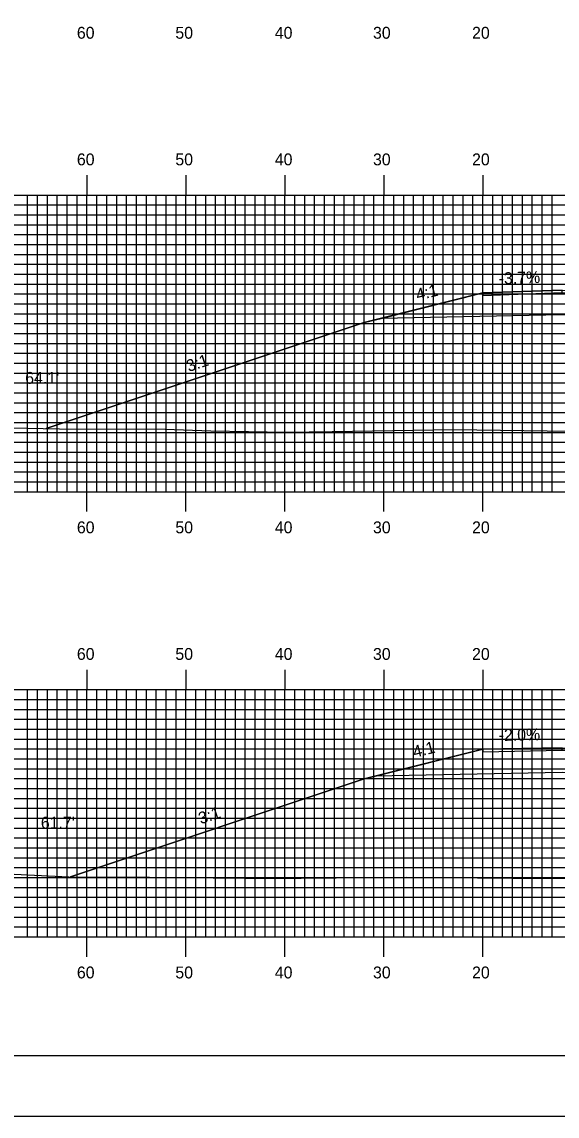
# Model space of a CAD drawing. Extents: x 1815309 to 1815652, y 442591 to 442811.
# Drawn here: x 1815408 to 1815462, y 442590.5 to 442701.2 of the extents above; entities that cross this region are included whole.
import ezdxf

# ---------------------------------------------------------------- set-up
doc = ezdxf.new("R2010")
doc.units = 0
for name, color, linetype in [('ANNOTATION', 7, 'Continuous'), ('BORDER', 7, 'Continuous'), ('D_Roadway_Centerline', 7, 'Continuous'), ('D_Roadway_Edge_Shoulder', 7, 'Continuous'), ('D_Roadway_SlopeLines', 7, 'Continuous'), ('D_Roadway_SubGrade', 7, 'Continuous'), ('D_Text_Standard', 7, 'Continuous'), ('H_V ANNOTATION', 7, 'Continuous'), ('MAJOR', 7, 'Continuous'), ('MINOR', 7, 'Continuous'), ('PLOT BOUNDARY', 7, 'Continuous'), ('S_Roadway_Centerline', 7, 'Continuous')]:
    doc.layers.add(name, color=color, linetype=linetype)

msp = doc.modelspace()

# ---------------------------------------------------------------- linework, layer by layer
at = {"layer": 'BORDER'}
msp.add_lwpolyline([(1815324.93, 442596.67), (1815644.93, 442596.67), (1815644.93, 442806.67), (1815324.93, 442806.67)], close=True, dxfattribs=at)
at = {"layer": 'D_Roadway_Centerline'}
for points in [[(1815410.41, 442660.06), (1815442.53, 442670.77), (1815444.25, 442671.2), (1815454.53, 442673.77), (1815462.53, 442674.06), (1815474.53, 442673.77), (1815486.53, 442673.48), (1815494.53, 442673.16), (1815505.06, 442670.53), (1815506.53, 442670.16), (1815538.16, 442659.62)], [(1815412.86, 442614.74), (1815442.53, 442624.63), (1815443.66, 442624.92), (1815454.53, 442627.63), (1815462.53, 442627.79), (1815474.53, 442627.27), (1815486.53, 442626.74), (1815494.53, 442626.39), (1815506.53, 442623.39), (1815506.66, 442623.36), (1815532.71, 442614.67)]]:
    msp.add_lwpolyline(points, dxfattribs=at)
at = {"layer": 'D_Roadway_Edge_Shoulder'}
for points in [[(1815462.53, 442674.06), (1815454.53, 442673.77), (1815454.53, 442673.52), (1815462.53, 442673.81)], [(1815462.53, 442627.79), (1815454.53, 442627.63), (1815454.53, 442627.38), (1815462.53, 442627.54)]]:
    msp.add_lwpolyline(points, close=True, dxfattribs=at)
at = {"layer": 'D_Roadway_SlopeLines'}
for points in [[(1815454.53, 442673.77), (1815442.53, 442670.77), (1815410.41, 442660.06)], [(1815454.53, 442627.63), (1815442.53, 442624.63), (1815412.86, 442614.74)]]:
    msp.add_lwpolyline(points, dxfattribs=at)
at = {"layer": 'D_Roadway_SubGrade'}
for points in [[(1815462.53, 442671.56), (1815444.25, 442671.2), (1815454.53, 442673.77), (1815454.53, 442673.52), (1815462.53, 442673.81), (1815474.53, 442673.52), (1815486.53, 442673.23), (1815494.53, 442672.91), (1815494.53, 442673.16), (1815505.06, 442670.53), (1815486.53, 442670.98), (1815474.53, 442671.27)], [(1815462.53, 442625.29), (1815443.66, 442624.92), (1815454.53, 442627.63), (1815454.53, 442627.38), (1815462.53, 442627.54), (1815474.53, 442627.02), (1815486.53, 442626.49), (1815494.53, 442626.14), (1815494.53, 442626.39), (1815506.66, 442623.36), (1815486.53, 442624.24), (1815474.53, 442624.77)]]:
    msp.add_lwpolyline(points, close=True, dxfattribs=at)
at = {"layer": 'MAJOR'}
for p, q in [((1815414.53, 442685.67), (1815414.53, 442683.67)), ((1815424.53, 442685.67), (1815424.53, 442683.67)), ((1815434.53, 442685.67), (1815434.53, 442683.67)), ((1815444.53, 442685.67), (1815444.53, 442683.67)), ((1815454.53, 442685.67), (1815454.53, 442683.67)), ((1815334.53, 442683.67), (1815614.53, 442683.67)), ((1815334.53, 442683.67), (1815614.53, 442683.67)), ((1815414.53, 442653.67), (1815414.53, 442683.67)), ((1815424.53, 442653.67), (1815424.53, 442683.67)), ((1815434.53, 442653.67), (1815434.53, 442683.67)), ((1815444.53, 442653.67), (1815444.53, 442683.67)), ((1815454.53, 442653.67), (1815454.53, 442683.67)), ((1815334.53, 442678.67), (1815614.53, 442678.67)), ((1815334.53, 442673.67), (1815614.53, 442673.67)), ((1815334.53, 442668.67), (1815614.53, 442668.67)), ((1815334.53, 442663.67), (1815614.53, 442663.67)), ((1815334.53, 442658.67), (1815614.53, 442658.67)), ((1815334.53, 442653.67), (1815614.53, 442653.67)), ((1815334.53, 442653.67), (1815614.53, 442653.67)), ((1815414.53, 442651.66), (1815414.53, 442653.67)), ((1815424.53, 442651.66), (1815424.53, 442653.67)), ((1815434.53, 442651.66), (1815434.53, 442653.67)), ((1815444.53, 442651.66), (1815444.53, 442653.67)), ((1815454.53, 442651.66), (1815454.53, 442653.67)), ((1815414.53, 442635.67), (1815414.53, 442633.67)), ((1815424.53, 442635.67), (1815424.53, 442633.67)), ((1815434.53, 442635.67), (1815434.53, 442633.67)), ((1815444.53, 442635.67), (1815444.53, 442633.67)), ((1815454.53, 442635.67), (1815454.53, 442633.67)), ((1815334.53, 442633.67), (1815614.53, 442633.67)), ((1815334.53, 442633.67), (1815614.53, 442633.67)), ((1815414.53, 442608.67), (1815414.53, 442633.67)), ((1815424.53, 442608.67), (1815424.53, 442633.67)), ((1815434.53, 442608.67), (1815434.53, 442633.67)), ((1815444.53, 442608.67), (1815444.53, 442633.67)), ((1815454.53, 442608.67), (1815454.53, 442633.67)), ((1815334.53, 442628.67), (1815614.53, 442628.67)), ((1815334.53, 442623.67), (1815614.53, 442623.67)), ((1815334.53, 442618.67), (1815614.53, 442618.67)), ((1815334.53, 442613.67), (1815614.53, 442613.67)), ((1815334.53, 442608.67), (1815614.53, 442608.67)), ((1815334.53, 442608.67), (1815614.53, 442608.67)), ((1815414.53, 442606.66), (1815414.53, 442608.67)), ((1815424.53, 442606.66), (1815424.53, 442608.67)), ((1815434.53, 442606.66), (1815434.53, 442608.67)), ((1815444.53, 442606.66), (1815444.53, 442608.67)), ((1815454.53, 442606.66), (1815454.53, 442608.67))]:
    msp.add_line(p, q, dxfattribs=at)
at = {"layer": 'MINOR'}
for p, q in [((1815408.53, 442653.67), (1815408.53, 442683.67)), ((1815409.53, 442653.67), (1815409.53, 442683.67)), ((1815410.53, 442653.67), (1815410.53, 442683.67)), ((1815411.53, 442653.67), (1815411.53, 442683.67)), ((1815412.53, 442653.67), (1815412.53, 442683.67)), ((1815413.53, 442653.67), (1815413.53, 442683.67)), ((1815415.53, 442653.67), (1815415.53, 442683.67)), ((1815416.53, 442653.67), (1815416.53, 442683.67)), ((1815417.53, 442653.67), (1815417.53, 442683.67)), ((1815418.53, 442653.67), (1815418.53, 442683.67)), ((1815419.53, 442653.67), (1815419.53, 442683.67)), ((1815420.53, 442653.67), (1815420.53, 442683.67)), ((1815421.53, 442653.67), (1815421.53, 442683.67)), ((1815422.53, 442653.67), (1815422.53, 442683.67)), ((1815423.53, 442653.67), (1815423.53, 442683.67)), ((1815425.53, 442653.67), (1815425.53, 442683.67)), ((1815426.53, 442653.67), (1815426.53, 442683.67)), ((1815427.53, 442653.67), (1815427.53, 442683.67)), ((1815428.53, 442653.67), (1815428.53, 442683.67)), ((1815429.53, 442653.67), (1815429.53, 442683.67)), ((1815430.53, 442653.67), (1815430.53, 442683.67)), ((1815431.53, 442653.67), (1815431.53, 442683.67)), ((1815432.53, 442653.67), (1815432.53, 442683.67)), ((1815433.53, 442653.67), (1815433.53, 442683.67)), ((1815435.53, 442653.67), (1815435.53, 442683.67)), ((1815436.53, 442653.67), (1815436.53, 442683.67)), ((1815437.53, 442653.67), (1815437.53, 442683.67)), ((1815438.53, 442653.67), (1815438.53, 442683.67)), ((1815439.53, 442653.67), (1815439.53, 442683.67)), ((1815440.53, 442653.67), (1815440.53, 442683.67)), ((1815441.53, 442653.67), (1815441.53, 442683.67)), ((1815442.53, 442653.67), (1815442.53, 442683.67)), ((1815443.53, 442653.67), (1815443.53, 442683.67)), ((1815445.53, 442653.67), (1815445.53, 442683.67)), ((1815446.53, 442653.67), (1815446.53, 442683.67)), ((1815447.53, 442653.67), (1815447.53, 442683.67)), ((1815448.53, 442653.67), (1815448.53, 442683.67)), ((1815449.53, 442653.67), (1815449.53, 442683.67)), ((1815450.53, 442653.67), (1815450.53, 442683.67)), ((1815451.53, 442653.67), (1815451.53, 442683.67)), ((1815452.53, 442653.67), (1815452.53, 442683.67)), ((1815453.53, 442653.67), (1815453.53, 442683.67)), ((1815455.53, 442653.67), (1815455.53, 442683.67)), ((1815456.53, 442653.67), (1815456.53, 442683.67)), ((1815457.53, 442653.67), (1815457.53, 442683.67)), ((1815458.53, 442653.67), (1815458.53, 442683.67)), ((1815459.53, 442653.67), (1815459.53, 442683.67)), ((1815460.53, 442653.67), (1815460.53, 442683.67)), ((1815461.53, 442653.67), (1815461.53, 442683.67)), ((1815334.53, 442682.67), (1815614.53, 442682.67)), ((1815334.53, 442681.67), (1815614.53, 442681.67)), ((1815334.53, 442680.67), (1815614.53, 442680.67)), ((1815334.53, 442679.67), (1815614.53, 442679.67)), ((1815334.53, 442677.67), (1815614.53, 442677.67)), ((1815334.53, 442676.67), (1815614.53, 442676.67)), ((1815334.53, 442675.67), (1815614.53, 442675.67)), ((1815334.53, 442674.67), (1815614.53, 442674.67)), ((1815334.53, 442672.67), (1815614.53, 442672.67)), ((1815334.53, 442671.67), (1815614.53, 442671.67)), ((1815334.53, 442670.67), (1815614.53, 442670.67)), ((1815334.53, 442669.67), (1815614.53, 442669.67)), ((1815334.53, 442667.67), (1815614.53, 442667.67)), ((1815334.53, 442666.67), (1815614.53, 442666.67)), ((1815334.53, 442665.67), (1815614.53, 442665.67)), ((1815334.53, 442664.67), (1815614.53, 442664.67)), ((1815334.53, 442662.67), (1815614.53, 442662.67)), ((1815334.53, 442661.67), (1815614.53, 442661.67)), ((1815334.53, 442660.67), (1815614.53, 442660.67)), ((1815334.53, 442659.67), (1815614.53, 442659.67)), ((1815334.53, 442657.67), (1815614.53, 442657.67)), ((1815334.53, 442656.67), (1815614.53, 442656.67)), ((1815334.53, 442655.67), (1815614.53, 442655.67)), ((1815334.53, 442654.67), (1815614.53, 442654.67)), ((1815408.53, 442608.67), (1815408.53, 442633.67)), ((1815409.53, 442608.67), (1815409.53, 442633.67)), ((1815410.53, 442608.67), (1815410.53, 442633.67)), ((1815411.53, 442608.67), (1815411.53, 442633.67)), ((1815412.53, 442608.67), (1815412.53, 442633.67)), ((1815413.53, 442608.67), (1815413.53, 442633.67)), ((1815415.53, 442608.67), (1815415.53, 442633.67)), ((1815416.53, 442608.67), (1815416.53, 442633.67)), ((1815417.53, 442608.67), (1815417.53, 442633.67)), ((1815418.53, 442608.67), (1815418.53, 442633.67)), ((1815419.53, 442608.67), (1815419.53, 442633.67)), ((1815420.53, 442608.67), (1815420.53, 442633.67)), ((1815421.53, 442608.67), (1815421.53, 442633.67)), ((1815422.53, 442608.67), (1815422.53, 442633.67)), ((1815423.53, 442608.67), (1815423.53, 442633.67)), ((1815425.53, 442608.67), (1815425.53, 442633.67)), ((1815426.53, 442608.67), (1815426.53, 442633.67)), ((1815427.53, 442608.67), (1815427.53, 442633.67)), ((1815428.53, 442608.67), (1815428.53, 442633.67)), ((1815429.53, 442608.67), (1815429.53, 442633.67)), ((1815430.53, 442608.67), (1815430.53, 442633.67)), ((1815431.53, 442608.67), (1815431.53, 442633.67)), ((1815432.53, 442608.67), (1815432.53, 442633.67)), ((1815433.53, 442608.67), (1815433.53, 442633.67)), ((1815435.53, 442608.67), (1815435.53, 442633.67)), ((1815436.53, 442608.67), (1815436.53, 442633.67)), ((1815437.53, 442608.67), (1815437.53, 442633.67)), ((1815438.53, 442608.67), (1815438.53, 442633.67)), ((1815439.53, 442608.67), (1815439.53, 442633.67)), ((1815440.53, 442608.67), (1815440.53, 442633.67)), ((1815441.53, 442608.67), (1815441.53, 442633.67)), ((1815442.53, 442608.67), (1815442.53, 442633.67)), ((1815443.53, 442608.67), (1815443.53, 442633.67)), ((1815445.53, 442608.67), (1815445.53, 442633.67)), ((1815446.53, 442608.67), (1815446.53, 442633.67)), ((1815447.53, 442608.67), (1815447.53, 442633.67)), ((1815448.53, 442608.67), (1815448.53, 442633.67)), ((1815449.53, 442608.67), (1815449.53, 442633.67)), ((1815450.53, 442608.67), (1815450.53, 442633.67)), ((1815451.53, 442608.67), (1815451.53, 442633.67)), ((1815452.53, 442608.67), (1815452.53, 442633.67)), ((1815453.53, 442608.67), (1815453.53, 442633.67)), ((1815455.53, 442608.67), (1815455.53, 442633.67)), ((1815456.53, 442608.67), (1815456.53, 442633.67)), ((1815457.53, 442608.67), (1815457.53, 442633.67)), ((1815458.53, 442608.67), (1815458.53, 442633.67)), ((1815459.53, 442608.67), (1815459.53, 442633.67)), ((1815460.53, 442608.67), (1815460.53, 442633.67)), ((1815461.53, 442608.67), (1815461.53, 442633.67)), ((1815334.53, 442632.67), (1815614.53, 442632.67)), ((1815334.53, 442631.67), (1815614.53, 442631.67)), ((1815334.53, 442630.67), (1815614.53, 442630.67)), ((1815334.53, 442629.67), (1815614.53, 442629.67)), ((1815334.53, 442627.67), (1815614.53, 442627.67)), ((1815334.53, 442626.67), (1815614.53, 442626.67)), ((1815334.53, 442625.67), (1815614.53, 442625.67)), ((1815334.53, 442624.67), (1815614.53, 442624.67)), ((1815334.53, 442622.67), (1815614.53, 442622.67)), ((1815334.53, 442621.67), (1815614.53, 442621.67)), ((1815334.53, 442620.67), (1815614.53, 442620.67)), ((1815334.53, 442619.67), (1815614.53, 442619.67)), ((1815334.53, 442617.67), (1815614.53, 442617.67)), ((1815334.53, 442616.67), (1815614.53, 442616.67)), ((1815334.53, 442615.67), (1815614.53, 442615.67)), ((1815334.53, 442614.67), (1815614.53, 442614.67)), ((1815334.53, 442612.67), (1815614.53, 442612.67)), ((1815334.53, 442611.67), (1815614.53, 442611.67)), ((1815334.53, 442610.67), (1815614.53, 442610.67)), ((1815334.53, 442609.67), (1815614.53, 442609.67))]:
    msp.add_line(p, q, dxfattribs=at)
at = {"layer": 'PLOT BOUNDARY'}
msp.add_lwpolyline([(1815308.75, 442590.55), (1815648.75, 442590.55), (1815648.75, 442810.55), (1815308.75, 442810.55)], close=True, dxfattribs=at)
at = {"layer": 'S_Roadway_Centerline'}
for points in [[(1815400.23, 442660.28), (1815411.74, 442660.03), (1815422.42, 442659.98), (1815427.06, 442659.83), (1815434.65, 442659.71), (1815439.29, 442659.76), (1815451.58, 442659.96), (1815465.79, 442659.75), (1815469.34, 442659.78), (1815479.38, 442659.77), (1815484.93, 442659.79), (1815492.58, 442659.87), (1815502.45, 442659.67), (1815518.01, 442659.62), (1815518.54, 442659.62), (1815518.67, 442659.62), (1815518.89, 442659.62), (1815536.31, 442659.64)], [(1815398.89, 442615.41), (1815413.38, 442614.72), (1815420.85, 442614.69), (1815430.49, 442614.62), (1815436.18, 442614.61), (1815446.82, 442614.7), (1815457.56, 442614.62), (1815463.97, 442614.59), (1815477.04, 442614.86), (1815481.53, 442614.9), (1815490.04, 442614.81), (1815504.11, 442614.67), (1815514.26, 442614.66), (1815516.61, 442614.68), (1815524.4, 442614.66), (1815532.52, 442614.67), (1815544, 442614.65)]]:
    msp.add_lwpolyline(points, dxfattribs=at)

# ---------------------------------------------------------------- texts
at = {"layer": 'ANNOTATION'}
for s, rotation, p in [('-3.7%', 2.1075, (1815456.15, 442674.63)), ('4:1', 14.0362, (1815447.93, 442672.98)), ('3:1', 18.4348, (1815424.81, 442665.77)), ('-2.0%', 1.1458, (1815456.14, 442628.47)), ('4:1', 14.0362, (1815447.63, 442626.77)), ('3:1', 18.4348, (1815426.03, 442620.04))]:
    msp.add_text(s, height=1.2, rotation=rotation, dxfattribs=at).set_placement(p)
at = {"layer": 'D_Text_Standard'}
for s, p in [("64.1'", (1815408.29, 442664.58)), ("61.7'", (1815409.87, 442619.61))]:
    msp.add_text(s, height=1.2, dxfattribs=at).set_placement(p)
at = {"layer": 'H_V ANNOTATION'}
for s, p in [('60', (1815413.51, 442699.47)), ('50', (1815423.46, 442699.47)), ('40', (1815433.51, 442699.47)), ('30', (1815443.43, 442699.47)), ('20', (1815453.44, 442699.47)), ('60', (1815413.51, 442686.67)), ('50', (1815423.46, 442686.67)), ('40', (1815433.51, 442686.67)), ('30', (1815443.43, 442686.67)), ('20', (1815453.44, 442686.67)), ('60', (1815413.51, 442649.47)), ('50', (1815423.46, 442649.47)), ('40', (1815433.51, 442649.47)), ('30', (1815443.43, 442649.47)), ('20', (1815453.44, 442649.47)), ('60', (1815413.51, 442636.67)), ('50', (1815423.46, 442636.67)), ('40', (1815433.51, 442636.67)), ('30', (1815443.43, 442636.67)), ('20', (1815453.44, 442636.67)), ('60', (1815413.51, 442604.47)), ('50', (1815423.46, 442604.47)), ('40', (1815433.51, 442604.47)), ('30', (1815443.43, 442604.47)), ('20', (1815453.44, 442604.47))]:
    msp.add_text(s, height=1.2, dxfattribs=at).set_placement(p)

doc.saveas('drawing.dxf')
